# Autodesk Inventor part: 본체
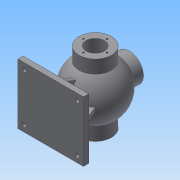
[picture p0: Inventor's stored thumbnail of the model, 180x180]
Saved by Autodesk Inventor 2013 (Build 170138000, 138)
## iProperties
Created: 2018-06
Part Number: 본체
Material: 일반
Document SubType Name: Modeling
Designer: Administrator
Density: 1 g/cm^3
Author: Administrator
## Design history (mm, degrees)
sketch "스케치1"
  geometry: L1 (31, -42.988)-(31, -68); L2 (31, -68)-(0, -68); L3 (0, -68)-(0, 68); L4 (0, 68)-(31, 68); L5 (31, 68)-(31, 42.988); A1 r 53 centre (0, 0) between (31, -42.988) and (31, 42.988); 2 further points
  constraints: 10 end point, 2 coincident, 2 parallel, 2 point on circle, 1 centre point, 1 collinear, 1 midpoint, 1 perpendicular, 1 vertical
  dimensions: "d0" = 106 diameter of A1; "d1" = 62 diameter of L1.end L3; "d2" = 62 diameter of L4.end L3; "d3" = 136 distance of L2.end L3.end
revolve "회전1" sketch "스케치1" stored, may be unused: angle "d4" = 90 deg
sketch "스케치2"
  geometry: L1 (-31, 68)-(31, 68) reference; L2 (31, 68)-(31, 42.988) reference; L3 (31, -42.988)-(31, -68) reference; L4 (31, -68)-(-31, -68) reference; L5 (-31, -68)-(-31, -42.988) reference; L6 (-31, 42.988)-(-31, 68) reference; L7 (17.5, -39.278)-(17.5, -50.25); L8 (17.5, -50.25)-(18.5, -50.25); L9 (18.5, -50.25)-(18.5, -52); L10 (18.5, -52)-(17.5, -52); L11 (17.5, -52)-(17.5, -68); L12 (17.5, 39.278)-(17.5, 68); L13 (17.5, 68)-(0, 68); L14 (0, 68)-(0, -68); L15 (17.5, -68)-(0, -68); A1 r 53 centre (0, 0) between (31, -42.988) and (31, 42.988) reference; A2 r 53 centre (0, 0) between (-31, 42.988) and (-31, -42.988) reference; A3 r 43 centre (0, 0) between (17.5, -39.278) and (17.5, 39.278); 1 further point
  constraints: 18 end point, 3 parallel, 2 collinear, 2 midpoint, 2 perpendicular, 2 point on circle, 2 point on line, 1 centre point, 1 coincident
  dimensions: "d5" = 86 diameter of A3; "d6" = 35 diameter of L12.end L14; "d7" = 35 diameter of L11.end L14; "d8" = 35 diameter of L7 L14; "d10" = 1.75 distance of L8.end L9.end; "d11" = 16 distance of L10.end L11.end; "d12" = 37 diameter of L9 L14
revolve "회전2" sketch "스케치2" stored, may be unused: angle "d13" = 90 deg
node "작업 평면1"
sketch "스케치3"
  geometry: C1 r 27 at (0, 0); 1 further point
  constraints: 1 centre point, 1 coincident
  dimensions: "d15" = 54 diameter of C1
extrude "돌출1" join sketch "스케치3" stored distance "d16" = 10; taper "d17" = 0 deg
sketch "스케치5"
  geometry: C1 r 27 at (0, 0) reference; C2 r 13 at (0, 0)
  constraints: 1 centre point, 1 coincident
  dimensions: "d18" = 26 diameter of C2
extrude "돌출2" cut sketch "스케치5" stored distance "d19" = 10; taper "d20" = 0 deg
node "작업 평면2"
sketch "스케치6"
  geometry: L1 (-62.5, 57.5)-(62.5, 57.5); L2 (62.5, 57.5)-(62.5, -57.5); L3 (62.5, -57.5)-(-62.5, -57.5); L4 (-62.5, -57.5)-(-62.5, 57.5); L5 (-62.5, 57.5)-(62.5, -57.5); L6 (62.5, 57.5)-(-62.5, -57.5); 1 further point
  constraints: 12 end point, 2 midpoint, 2 parallel, 1 horizontal, 1 perpendicular
  dimensions: "d22" = 125 distance of L2.end L3.end; "d23" = 115 distance of L1.end L2.end
extrude "돌출3" join sketch "스케치6" distance "d24" = 10; taper "d25" = 0 deg
sketch "스케치7"
  geometry: L1 (-62.5, -57.5)-(62.5, -57.5) reference; L2 (62.5, -57.5)-(62.5, 57.5) reference; L3 (62.5, 57.5)-(-62.5, 57.5) reference; L4 (-62.5, 57.5)-(-62.5, -57.5) reference; L5 (52.5, -4)-(-52.5, -4); L6 (-52.5, -4)-(-52.5, 4); L7 (-52.5, 4)-(52.5, 4); L8 (52.5, 4)-(52.5, -4); L9 (52.5, -4)-(-52.5, 4); L10 (-52.5, -4)-(52.5, 4); L11 (4, -47.5)-(-4, -47.5); L12 (-4, -47.5)-(-4, 47.5); L13 (-4, 47.5)-(4, 47.5); L14 (4, 47.5)-(4, -47.5); L15 (4, -47.5)-(-4, 47.5); L16 (-4, -47.5)-(4, 47.5); 3 further points
  constraints: 24 end point, 6 midpoint, 4 parallel, 2 horizontal, 2 perpendicular
  dimensions: "d26" = 8 distance of L7.end L5.start; "d28" = 8 distance of L12.end L13.end; "d29" = 10 distance between parallel lines of L3 L13; "d30" = 10 distance between parallel lines of L1 L11 (derived); "d31" = 10 distance between parallel lines of L2 L8; "d32" = 10 distance between parallel lines of L4 L6 (derived)
extrude "돌출4" join sketch "스케치7" stored distance "d33" = 10; taper "d34" = 0 deg
feature "면 기울기1" dims angle "d35" = 22 deg
sketch "스케치8"
  geometry: C1 r 4 at (-50.5, 45.5); C2 r 4 at (50.5, 45.5); C3 r 4 at (-50.5, -45.5); C4 r 4 at (50.5, -45.5); 1 further point
  constraints: 4 centre point, 2 horizontal alignment, 2 vertical alignment
  dimensions: "d36" = 8 diameter of C1; "d37" = 8 diameter of C2; "d38" = 8 diameter of C3; "d39" = 8 diameter of C4; "d40" = 101 distance of C2.centre C1.centre; "d41" = 50.5 horizontal distance of point (0, 0) C1.centre; "d42" = 91 distance of C4.centre C2.centre; "d43" = 45.5 vertical distance of point (0, 0) C2.centre
extrude "돌출5" cut sketch "스케치8" stored distance "d44" = 10; taper "d45" = 0 deg
sketch "스케치9"
  geometry: C1 r 4 at (-50.5, -45.5) reference; C2 r 4 at (-50.5, 45.5) reference; C3 r 4 at (50.5, 45.5) reference; C4 r 4 at (50.5, -45.5) reference; C5 r 6 at (-50.5, 45.5); C6 r 6 at (50.5, 45.5); C7 r 6 at (50.5, -45.5); C8 r 6 at (-50.5, -45.5); 1 further point
  constraints: 4 centre point, 4 coincident
  dimensions: "d46" = 12 diameter of C5; "d47" = 12 diameter of C6; "d48" = 12 diameter of C7; "d49" = 12 diameter of C8
extrude "돌출6" cut sketch "스케치9" distance "d50" = 3; taper "d51" = 0 deg
sketch "스케치10" dims "d52" = 45
  geometry: C1 r 31 at (0, 0) reference; 2 further points
  constraints: 2 vertical alignment, 1 coincident, 2 other
hole "구멍1" sketch "스케치10" at (0, 22.5) diameter "d53" = 3.242; stored, may be unused: countersink angle "d57" = 90 deg, drill point angle "d59" = 118 deg; dims "d54" = 12, "d55" = 4, "d56" = 2, "d58" = 15
sketch "스케치11" dims "d63" = 48
  geometry: C1 r 17.5 at (0, 0) reference; C2 r 31 at (0, 0) reference; 2 further points
  constraints: 2 vertical alignment, 1 coincident, 2 other
hole "구멍2" sketch "스케치11" at (0, 24) diameter "d64" = 3.242; stored, may be unused: countersink angle "d68" = 90 deg, drill point angle "d70" = 118 deg; dims "d65" = 16, "d66" = 4, "d67" = 2, "d69" = 19
sketch "스케치12" dims "d74" = 40
  geometry: C1 r 27 at (0, 0) reference; C2 r 13 at (0, 0) reference; 2 further points
  constraints: 2 vertical alignment, 1 coincident, 2 other
hole "구멍3" sketch "스케치12" at (0, 20) diameter "d75" = 3.242; stored, may be unused: countersink angle "d79" = 90 deg, drill point angle "d81" = 118 deg; dims "d76" = 9, "d77" = 4, "d78" = 2, "d80" = 11
node "솔리드1"
pattern_circular "원형 패턴1" dims angle "d61" = 360 deg
pattern_circular "원형 패턴2" dims angle "d72" = 360 deg
pattern_circular "원형 패턴3" dims angle "d83" = 360 deg
node "절단 모서리 투영1"
other parameters: "d14" = 65, "d21" = -85
